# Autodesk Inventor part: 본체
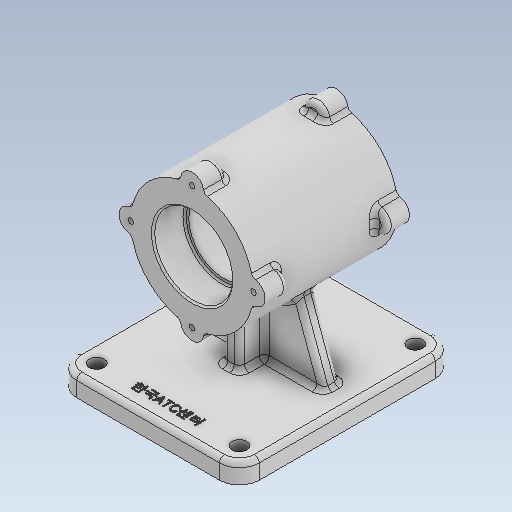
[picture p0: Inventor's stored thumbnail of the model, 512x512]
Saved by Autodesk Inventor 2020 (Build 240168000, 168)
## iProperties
Created: 2022-11
Part Number: 본체
Material: 일반
Document SubType Name: Modeling
Designer: owner
Density: 1 g/cm^3
Appearance: 기본값
Mass: 450.145 g
Surface Area: 796.917 cm^2
Volume: 450.145 cm^3
Author: owner
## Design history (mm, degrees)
sketch "스케치1"
  geometry: C1 r 37 at (0, 0); 1 further point
  constraints: 1 centre point, 1 coincident
  dimensions: "d0" = 74 diameter of C1
extrude "돌출1" new body sketch "스케치1" stored distance "d1" = 87; taper "d2" = 0 deg
sketch "스케치2"
  geometry: C1 r 37 at (0, 0) reference; 2 further points
  constraints: 1 coincident
hole "구멍1" sketch "스케치2" at (0, 0) diameter "d3" = 42; stored, may be unused: countersink angle "d7" = 90 deg, drill point angle "d9" = 0 deg; dims "d4" = 6, "d5" = 47, "d6" = 19, "d8" = 10
sketch "스케치3"
  geometry: C1 r 21 at (0, 0) reference; C2 r 23.5 at (0, 0); 1 further point
  constraints: 1 centre point, 1 coincident
  dimensions: "d10" = 47 diameter of C2
extrude "돌출2" cut sketch "스케치3" distance "d11" = 19; taper "d12" = 0 deg
sketch "스케치4"
  geometry: C1 r 7 at (0, 37); 4 further points
  constraints: 1 centre point, 1 vertical alignment, 2 other
  dimensions: "d13" = 14 diameter of C1
extrude "돌출3" join sketch "스케치4" distance "d14" = 14; taper "d15" = 0 deg
sketch "스케치5"
  geometry: A1 r 7 centre (0, 37) between (6.969, 36.338) and (-6.969, 36.338) reference; 2 further points
  constraints: 1 coincident
hole "구멍2" sketch "스케치5" at (0, 37) diameter "d19" = 3.242; stored, may be unused: countersink angle "d23" = 90 deg, drill point angle "d25" = 118 deg; dims "d20" = 8, "d21" = 47, "d22" = 19, "d24" = 10
sketch "스케치6"
  geometry: L1 (-55, -70)-(55, -70); L2 (55, -70)-(55, -82); L3 (55, -82)-(-55, -82); L4 (-55, -82)-(-55, -70); 2 further points
  constraints: 8 end point, 2 parallel, 1 horizontal, 1 midpoint, 1 perpendicular, 1 vertical alignment
  dimensions: "d29" = 110 distance of L2.end L3.end; "d30" = 12 distance of L3.end L1.start; "d31" = 82 distance from line of point (0, 0) L3
extrude "돌출4" join sketch "스케치6" distance "d32" = 70; taper "d33" = 0 deg
sketch "스케치7"
  geometry: L1 (-55, -70)-(55, -70) reference; L2 (-55, -82)-(-55, -70) reference; L3 (55, -70)-(55, -82) reference; L4 (55, -82)-(-55, -82) reference; 1 further point
extrude "돌출5" join sketch "스케치7" distance "d34" = 60; taper "d35" = 0 deg
fillet "모깎기1" dims "d36" = 12
sketch "스케치8"
  geometry: A1 r 12 centre (0, 12) between (-12, 12) and (0, 0) reference; A2 r 12 centre (86, 12) between (86, 0) and (98, 12) reference; A3 r 12 centre (86, 118) between (98, 118) and (86, 130) reference; A4 r 12 centre (0, 118) between (0, 130) and (-12, 118) reference; 5 further points
  constraints: 4 coincident
hole "구멍3" sketch "스케치8" at (0, 12), (86, 12), (86, 118), (0, 118) diameter "d37" = 9; stored, may be unused: countersink angle "d41" = 90 deg, drill point angle "d43" = 118 deg; dims "d38" = 8, "d39" = 47, "d40" = 19, "d42" = 10
sketch "스케치9"
  geometry: L1 (43, -70)-(55, -70) reference; L2 (-43, -70)-(43, -70) reference; L3 (-55, -70)-(-43, -70) reference; L4 (43, -70)-(-43, -70) reference; L5 (41, -70)-(25.336, -26.964); L6 (-25.336, -26.964)-(-41, -70); A1 r 37 centre (0, 0) between (6.969, -36.338) and (36.338, -6.969) reference; A2 r 37 centre (0, 0) between (-36.338, -6.969) and (-6.969, -36.338) reference; A3 r 37 centre (0, 0) between (-6.969, -36.338) and (6.969, -36.338) reference; 3 further points
  constraints: 4 end point, 2 point on circle, 2 point on line
  dimensions: "d44" = 14 distance of L5.start L1.end; "d45" = 14 distance of L3.start L6.end; "d46" = 110 deg angle of L1 L5; "d47" = 110 deg angle of L3 L6
extrude "돌출6" join sketch "스케치9" stored distance "d48" = 10; taper "d49" = 0 deg
sketch "스케치10"
  geometry: L1 (-70, -48)-(-70, 58) reference; L2 (-70, -48)-(-70, 58) reference; L3 (-70, 20)-(-48.714, 20); 1 further point
  constraints: 2 end point, 1 perpendicular, 1 point on line
  dimensions: "d50" = 20 vertical distance of L3.start point (0, 0)
feature "리브1" sketch "스케치10" dims "d51" = 1, "d52" = 10, "d53" = 0, "d54" = 0, "d55" = 1, "d56" = 1
fillet "모깎기2" dims "d57" = 3
fillet "모깎기3" dims "d58" = 3
fillet "모깎기4" dims "d62" = 3
fillet "모깎기5" dims "d63" = 3
fillet "모깎기6" dims "d70" = 3
fillet "모깎기7" dims "d71" = 3
sketch "스케치11"
  geometry: L1 (0, -3)-(86, -3) reference; C1 r 4.5 at (86, 9) reference; 3 further points
  constraints: 1 midpoint, 1 vertical alignment, 1 other
  dimensions: "d72" = 12 distance of point (43, -3) point (43, 9)
feature "엠보싱1" sketch "스케치11" dims "d2" = 0, "d73" = 0.5, "d74" = 0
fillet "모깎기8" dims "d78" = 1
chamfer "모따기3" distance "d79" = 1; stored, may be unused: second distance "d80" = 2, angle "d81" = 45 deg
node "솔리드1"
pattern_circular "원형 패턴1" dims angle "d17" = 360 deg
pattern_circular "원형 패턴2" dims angle "d27" = 360 deg
mirror "미러1"
mirror "미러2"
pattern_circular "원형 패턴3" dims angle "d60" = 360 deg
pattern_circular "원형 패턴4" dims angle "d65" = 360 deg
feature "A9D066F2-1C7D-4E18-AEED-F7BC21143FA4" dims "d3" = 42, "d4" = 6, "d5" = 47, "d6" = 19, "d7" = 90 deg, "d8" = 10, "d9" = 0
